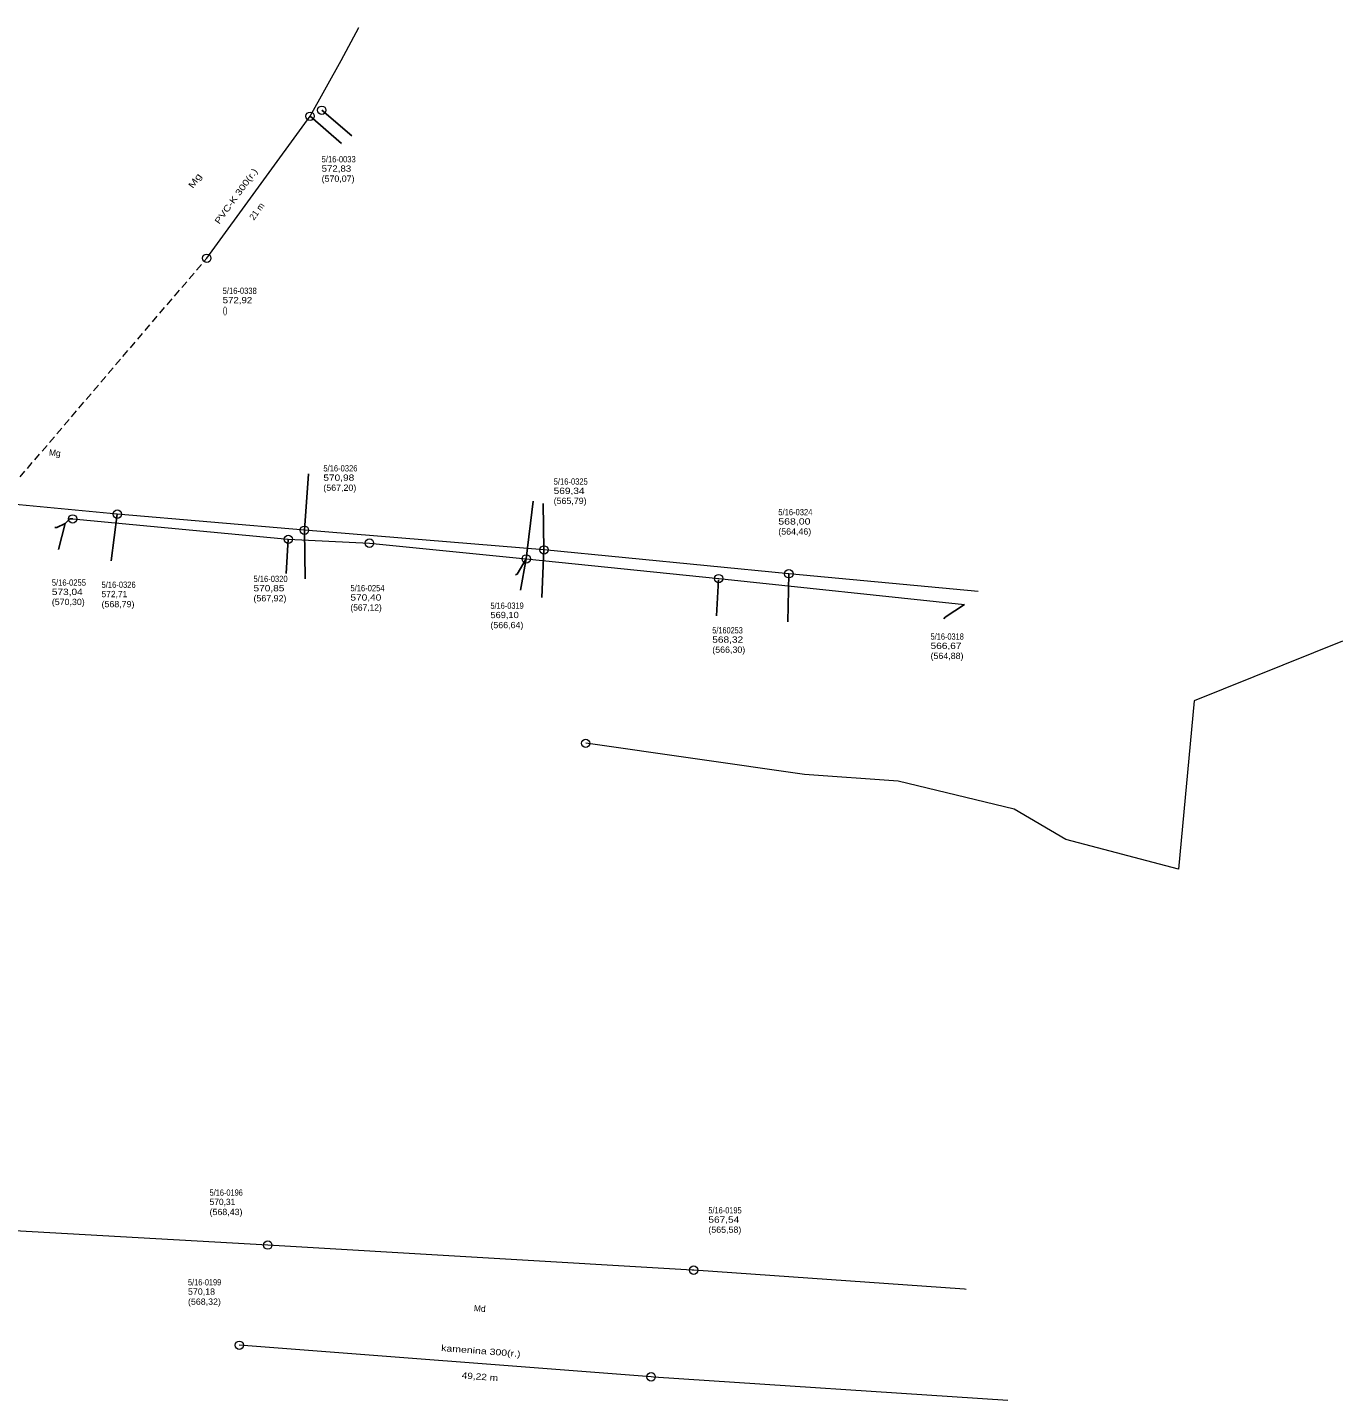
# Model space of a CAD drawing. Extents: x -710854 to -709799, y -1117012 to -1115891.
# Drawn here: x -709955.5 to -709798.8, y -1116102 to -1115938.3 of the extents above; entities that cross this region are included whole.
import ezdxf
from ezdxf.enums import TextEntityAlignment as Align

# ---------------------------------------------------------------- set-up
doc = ezdxf.new("R2010")
doc.units = 0
doc.header["$LTSCALE"] = 0.3
doc.linetypes.add('MEDIUM_DASHED', pattern=[4.5, 3, -1.5])
for name, color, linetype, lineweight in [('35', 7, 'Continuous', 25), ('36', 7, 'Continuous', 13), ('38', 7, 'Continuous', 13), ('44', 7, 'Continuous', 13)]:
    doc.layers.add(name, color=color, linetype=linetype, lineweight=lineweight)
doc.layers.add('48', color=7, linetype='Continuous')

msp = doc.modelspace()

# ---------------------------------------------------------------- linework, layer by layer
at = {"layer": '35'}
for p, q in [((-709920.48, -1115948.16), (-709916.9, -1115951.21)), ((-709921.87, -1115948.88), (-709918.14, -1115952.14)), ((-709922.54, -1115998.23), (-709922.04, -1115991.51)), ((-709896.1, -1116001.65), (-709895.29, -1115994.75)), ((-709893.99, -1116000.57), (-709894.08, -1115995.04)), ((-709944.84, -1115996.31), (-709945.58, -1116001.89)), ((-709924.46, -1115999.31), (-709924.73, -1116003.4)), ((-709922.54, -1115998.23), (-709922.47, -1116004.02)), ((-709893.99, -1116000.57), (-709894.23, -1116006.25)), ((-709896.1, -1116001.65), (-709896.77, -1116005.38)), ((-709873.178, -1116004.134), (-709873.41, -1116008.45)), ((-709864.81, -1116003.41), (-709864.91, -1116009.16))]:
    msp.add_line(p, q, dxfattribs=at)
for points in [[(-709951.04, -1115997.42), (-709952.052, -1115997.906), (-709952.283, -1115997.906)], [(-709950.16, -1115996.88), (-709950.5, -1115996.86), (-709951.04, -1115997.42), (-709951.86, -1116000.54)], [(-709896.1, -1116001.65), (-709897.2, -1116003.45), (-709897.29, -1116003.515), (-709897.38, -1116003.58)], [(-709843.89, -1116007.09), (-709846.19, -1116008.61), (-709846.33, -1116008.77)]]:
    msp.add_lwpolyline(points, dxfattribs=at)
at = {"layer": '36'}
for p, q in [((-709950.16, -1115996.88), (-709924.46, -1115999.31)), ((-709924.46, -1115999.31), (-709914.79, -1115999.77)), ((-709914.79, -1115999.77), (-709896.1, -1116001.65)), ((-709896.1, -1116001.65), (-709873.17, -1116003.99)), ((-709873.17, -1116003.99), (-709843.89, -1116007.09))]:
    msp.add_line(p, q, dxfattribs=at)
msp.add_lwpolyline([(-709798.82, -1116011.46), (-709816.51, -1116018.58), (-709818.35, -1116038.62), (-709831.802, -1116035.08), (-709837.97, -1116031.49), (-709851.77, -1116028.13), (-709862.95, -1116027.36), (-709889.02, -1116023.63)], dxfattribs=at)
at = {"layer": '38'}
msp.add_line((-709934.18, -1115965.8), (-709921.87, -1115948.88), dxfattribs=at)
at = {"layer": '38', "linetype": 'MEDIUM_DASHED'}
msp.add_line((-709959.06, -1115994.96), (-709934.18, -1115965.8), dxfattribs=at)
at = {"layer": '38'}
for points in [[(-709921.87, -1115948.88), (-709918.15, -1115942.22), (-709916.07, -1115938.31), (-709916.056, -1115938.292)], [(-709893.99, -1116000.57), (-709922.54, -1115998.23), (-709944.84, -1115996.31), (-709959.06, -1115994.96)], [(-709842.26, -1116005.52), (-709864.81, -1116003.41), (-709893.99, -1116000.57)], [(-709876.147, -1116086.433), (-709876.321, -1116086.421), (-709926.911, -1116083.45), (-709970.468, -1116080.984)], [(-709843.678, -1116088.724), (-709843.871, -1116088.711), (-709876.147, -1116086.433)], [(-709838.713, -1116101.977), (-709880.925, -1116099.175), (-709881.225, -1116099.152), (-709930.301, -1116095.391)]]:
    msp.add_lwpolyline(points, dxfattribs=at)
at = {"layer": '44'}
for centre in [(-709921.87, -1115948.88), (-709920.48, -1115948.16), (-709934.18, -1115965.8), (-709944.84, -1115996.31), (-709950.16, -1115996.88), (-709922.54, -1115998.23), (-709924.46, -1115999.31), (-709914.79, -1115999.77), (-709893.99, -1116000.57), (-709896.1, -1116001.65), (-709873.17, -1116003.99), (-709864.81, -1116003.41), (-709889.02, -1116023.63), (-709926.911, -1116083.45), (-709876.147, -1116086.433), (-709930.301, -1116095.391), (-709881.225, -1116099.152)]:
    msp.add_circle(centre, 0.5, dxfattribs=at)

# ---------------------------------------------------------------- texts
at = {"layer": '48'}
for s, rotation, width, p in [('PVC-K 300(r.)', 53.96, 1.25, (-709930.3912, -1115958.6201)), ('Mg', 53.96, 1.35, (-709935.2848, -1115956.7806)), ('kamenina 300(r.)', 355.62, 1.25, (-709901.5376, -1116096.4326)), ('49,22 m', 355.62, 1.2, (-709901.6521, -1116099.5023))]:
    msp.add_text(s, height=0.75, rotation=rotation, dxfattribs=dict(at, width=width)).set_placement(p, align=Align.CENTER)
for s, width, p in [('5/16-0033', 0.9, (-709920.492, -1115954.379)), ('572,83 ', 1.15, (-709920.492, -1115955.489)), ('(570,07)', 1.05, (-709920.492, -1115956.689)), ('5/16-0338', 0.9, (-709932.287, -1115970.059)), ('()', 0.7, (-709932.287, -1115972.369)), ('572,92 ', 1.15, (-709932.287, -1115971.169)), ('5/16-0326', 0.9, (-709920.284, -1115991.221)), ('570,98 ', 1.2, (-709920.284, -1115992.332)), ('(567,20)', 1.05, (-709920.284, -1115993.532)), ('5/16-0325', 0.9, (-709892.837, -1115992.793)), ('569,34 ', 1.2, (-709892.837, -1115993.903)), ('(565,79)', 1.05, (-709892.837, -1115995.103)), ('5/16-0324', 0.9, (-709866.063, -1115996.441)), ('568,00 ', 1.25, (-709866.063, -1115997.551)), ('(564,46)', 1.05, (-709866.063, -1115998.751)), ('5/16-0255', 0.9, (-709952.644, -1116004.842)), ('5/16-0326', 0.9, (-709946.719, -1116005.098)), ('5/16-0320', 0.9, (-709928.61, -1116004.404)), ('573,04 ', 1.2, (-709952.644, -1116005.952)), ('570,85 ', 1.2, (-709928.61, -1116005.514)), ('(567,92)', 1.05, (-709928.61, -1116006.714)), ('5/16-0254', 0.9, (-709917.058, -1116005.503)), ('570,40 ', 1.2, (-709917.058, -1116006.613)), ('(570,30)', 1.05, (-709952.644, -1116007.152)), ('(568,79)', 1.05, (-709946.719, -1116007.408)), ('5/16-0319', 0.85, (-709900.371, -1116007.596)), ('569,10 ', 1.1, (-709900.371, -1116008.706)), ('(566,64)', 1.05, (-709900.371, -1116009.906)), ('5/160253', 0.8, (-709873.931, -1116010.53)), ('5/16-0318', 0.85, (-709847.917, -1116011.273)), ('568,32 ', 1.2, (-709873.931, -1116011.64)), ('(566,30)', 1.05, (-709873.931, -1116012.84)), ('566,67 ', 1.2, (-709847.917, -1116012.383)), ('(564,88)', 1.05, (-709847.917, -1116013.583)), ('5/16-0196', 0.85, (-709933.845, -1116077.563)), ('(568,43)', 1.05, (-709933.845, -1116079.873)), ('5/16-0195', 0.85, (-709874.398, -1116079.672)), ('567,54 ', 1.2, (-709874.398, -1116080.782)), ('(565,58)', 1.05, (-709874.398, -1116081.982)), ('5/16-0199', 0.85, (-709936.418, -1116088.254)), ('570,18 ', 1.05, (-709936.418, -1116089.364)), ('(568,32)', 1.05, (-709936.418, -1116090.564))]:
    msp.add_text(s, height=0.75, dxfattribs=dict(at, width=width)).set_placement(p)
for s, rotation, p in [('21 m', 53.96, (-709927.9104, -1115960.4291)), ('Mg', 354.58, (-709952.3169, -1115989.3726)), ('Md', 355.62, (-709901.6696, -1116091.3675))]:
    msp.add_text(s, height=0.75, rotation=rotation, dxfattribs=at).set_placement(p, align=Align.CENTER)
for s, p in [('572,71 ', (-709946.719, -1116006.208)), ('(567,12)', (-709917.058, -1116007.813)), ('570,31 ', (-709933.845, -1116078.673))]:
    msp.add_text(s, height=0.75, dxfattribs=at).set_placement(p)

doc.saveas('drawing.dxf')
